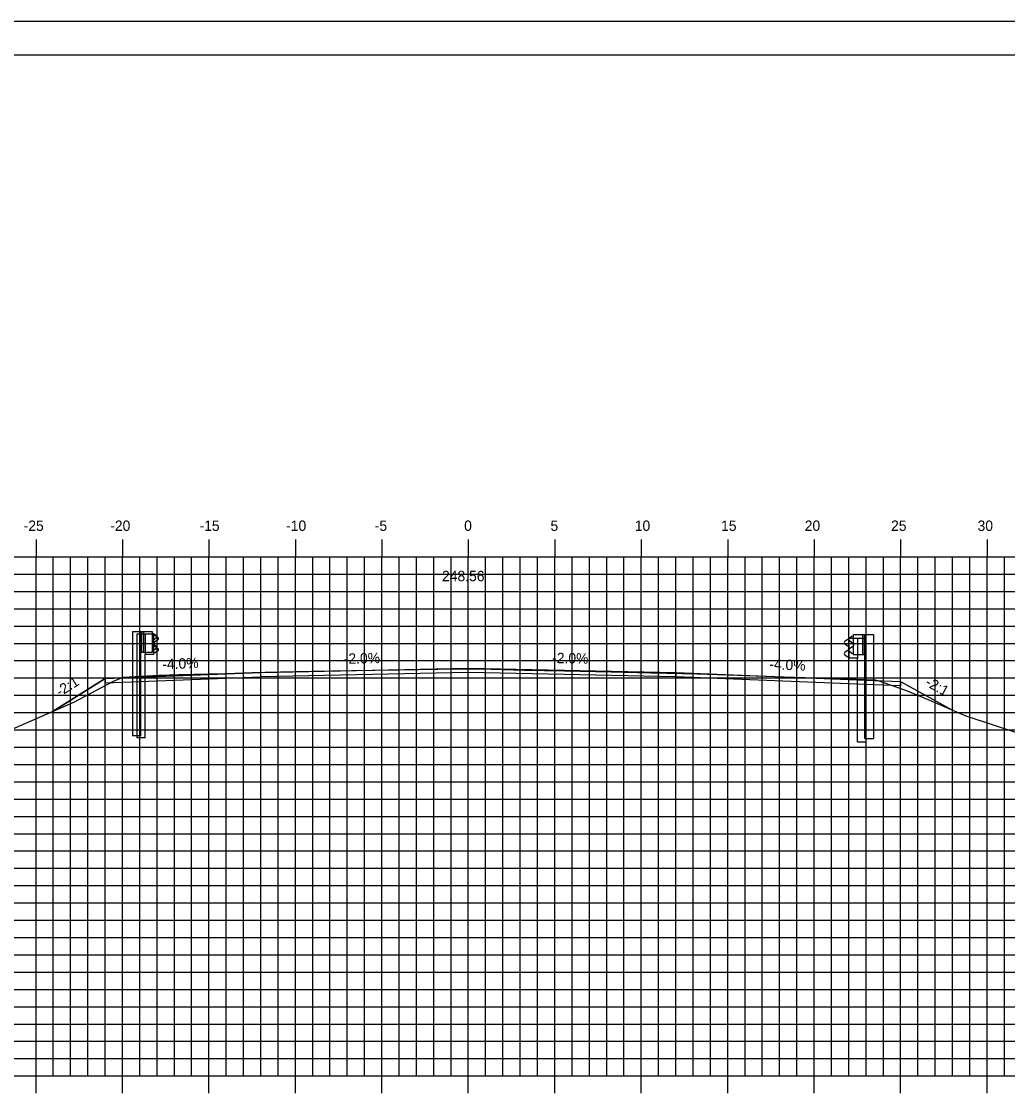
# Model space of a CAD drawing. Extents: x -22 to 1480, y -1511 to 8.
# Drawn here: x 162.3 to 219.3, y -1463.6 to -1401.4 of the extents above; entities that cross this region are included whole.
import ezdxf

# ---------------------------------------------------------------- set-up
doc = ezdxf.new("R2010")
doc.units = 0
for name, color, linetype in [('ANNOTATION', 7, 'Continuous'), ('BORDER', 7, 'Continuous'), ('D_Guardrail_Beam_Lt', 7, 'Continuous'), ('D_Guardrail_Beam_Rt', 7, 'Continuous'), ('D_Roadway_Centerline', 7, 'Continuous'), ('D_Roadway_Centerline_Text', 7, 'Continuous'), ('D_Roadway_Edge_Shoulder', 7, 'Continuous'), ('D_Roadway_Edge_TW', 7, 'Continuous'), ('D_Roadway_SlopeLines', 7, 'Continuous'), ('H_V ANNOTATION', 7, 'Continuous'), ('MAJOR', 7, 'Continuous'), ('MINOR', 7, 'Continuous'), ('PLOT BOUNDARY', 7, 'Continuous'), ('S_Guardrail_Beam', 7, 'Continuous'), ('S_Roadway_Centerline', 7, 'Continuous')]:
    doc.layers.add(name, color=color, linetype=linetype)

msp = doc.modelspace()

# ---------------------------------------------------------------- linework, layer by layer
at = {"layer": 'BORDER'}
msp.add_line((273.157, -1403.331), (113.157, -1403.331), dxfattribs=at)
at = {"layer": 'D_Guardrail_Beam_Lt'}
for p, q in [((168.727, -1436.668), (168.727, -1442.668)), ((169.198, -1436.668), (168.727, -1436.668)), ((169.886, -1436.668), (169.198, -1436.668)), ((169.198, -1436.668), (169.198, -1437.834)), ((169.261, -1436.668), (169.261, -1437.834)), ((169.365, -1436.668), (169.365, -1437.834)), ((169.886, -1437.834), (169.886, -1436.668)), ((169.886, -1436.751), (169.96, -1436.766)), ((170.119, -1437.015), (169.924, -1437.152)), ((169.976, -1436.772), (170.119, -1436.872)), ((169.96, -1437.737), (169.886, -1437.751)), ((169.89, -1437.216), (169.89, -1437.286)), ((169.924, -1437.351), (170.119, -1437.487)), ((170.119, -1437.63), (169.976, -1437.73)), ((169.198, -1437.834), (169.886, -1437.834)), ((169.219, -1442.668), (169.219, -1437.834)), ((169.219, -1442.668), (168.727, -1442.668))]:
    msp.add_line(p, q, dxfattribs=at)
for centre, major_axis, start_param, end_param in [((169.952, -1436.806), (0.0417, 0), 0.959931, 1.376053), ((170.069, -1436.944), (0.0877, 0), 5.323254, 7.243116), ((169.969, -1437.216), (-0.0789, 0), 5.323254, 6.283185), ((169.969, -1437.286), (-0.0789, 0), 6.283185, 7.243116), ((169.952, -1437.696), (0.0417, 0), 4.907132, 5.323254), ((170.069, -1437.558), (0.0877, 0), 5.323254, 7.243116)]:
    msp.add_ellipse(centre, major_axis=major_axis, ratio=0.995501, start_param=start_param, end_param=end_param, dxfattribs=at)
at = {"layer": 'D_Guardrail_Beam_Rt'}
for p, q in [((210.337, -1436.932), (210.194, -1437.032)), ((210.427, -1436.911), (210.353, -1436.926)), ((210.427, -1436.828), (211.115, -1436.828)), ((210.427, -1437.994), (210.427, -1436.828)), ((210.948, -1436.828), (210.948, -1437.994)), ((211.052, -1436.828), (211.052, -1437.994)), ((211.115, -1436.828), (211.586, -1436.828)), ((211.115, -1436.828), (211.115, -1437.994)), ((211.586, -1436.828), (211.586, -1442.828)), ((210.194, -1437.175), (210.389, -1437.312)), ((210.389, -1437.511), (210.194, -1437.647)), ((210.423, -1437.376), (210.423, -1437.446)), ((210.194, -1437.79), (210.337, -1437.89)), ((210.353, -1437.897), (210.427, -1437.911)), ((211.115, -1437.994), (210.427, -1437.994)), ((211.094, -1442.828), (211.094, -1437.994)), ((211.094, -1442.828), (211.586, -1442.828))]:
    msp.add_line(p, q, dxfattribs=at)
for centre, major_axis, start_param, end_param in [((210.244, -1437.104), (-0.0877, 0), 5.323254, 7.243116), ((210.361, -1436.966), (-0.0417, 0), 4.907132, 5.323254), ((210.244, -1437.718), (-0.0877, 0), 5.323254, 7.243116), ((210.344, -1437.376), (0.0789, 0), 0, 0.959931), ((210.344, -1437.446), (0.0789, 0), 5.323254, 6.283185), ((210.361, -1437.856), (-0.0417, 0), 0.959931, 1.376053)]:
    msp.add_ellipse(centre, major_axis=major_axis, ratio=0.995501, start_param=start_param, end_param=end_param, dxfattribs=at)
at = {"layer": 'D_Roadway_Centerline'}
msp.add_lwpolyline([(164.156, -1441.249), (167.156, -1439.371), (170.156, -1439.251), (176.156, -1439.011), (188.156, -1438.771), (200.156, -1439.011), (210.156, -1439.411), (213.156, -1439.531), (216.156, -1441.183)], dxfattribs=at)
at = {"layer": 'D_Roadway_Edge_Shoulder'}
for points in [[(176.156, -1439.011), (170.156, -1439.251), (170.156, -1439.251), (167.156, -1439.371), (167.156, -1439.621), (170.156, -1439.501), (170.156, -1439.501), (176.156, -1439.261)], [(200.156, -1439.011), (210.156, -1439.411), (210.156, -1439.411), (213.156, -1439.531), (213.156, -1439.781), (210.156, -1439.661), (210.156, -1439.661), (200.156, -1439.261)]]:
    msp.add_lwpolyline(points, close=True, dxfattribs=at)
at = {"layer": 'D_Roadway_Edge_TW'}
msp.add_lwpolyline([(176.156, -1439.261), (176.156, -1439.011), (188.156, -1438.771), (200.156, -1439.011), (200.156, -1439.261), (188.156, -1439.021)], close=True, dxfattribs=at)
at = {"layer": 'D_Roadway_SlopeLines'}
for points in [[(167.156, -1439.371), (164.156, -1441.249)], [(213.156, -1439.531), (216.156, -1441.183)]]:
    msp.add_lwpolyline(points, dxfattribs=at)
at = {"layer": 'MAJOR'}
for p, q in [((163.156, -1431.329), (163.156, -1432.331)), ((168.156, -1431.329), (168.156, -1432.331)), ((173.156, -1431.329), (173.156, -1432.331)), ((178.156, -1431.329), (178.156, -1432.331)), ((183.156, -1431.329), (183.156, -1432.331)), ((188.156, -1431.329), (188.156, -1432.331)), ((193.156, -1431.329), (193.156, -1432.331)), ((198.156, -1431.329), (198.156, -1432.331)), ((203.156, -1431.329), (203.156, -1432.331)), ((208.156, -1431.329), (208.156, -1432.331)), ((213.156, -1431.329), (213.156, -1432.331)), ((218.156, -1431.329), (218.156, -1432.331)), ((118.156, -1432.331), (258.156, -1432.331)), ((118.156, -1432.331), (258.156, -1432.331)), ((163.156, -1462.331), (163.156, -1432.331)), ((168.156, -1462.331), (168.156, -1432.331)), ((173.156, -1462.331), (173.156, -1432.331)), ((178.156, -1462.331), (178.156, -1432.331)), ((183.156, -1462.331), (183.156, -1432.331)), ((188.156, -1462.331), (188.156, -1432.331)), ((193.156, -1462.331), (193.156, -1432.331)), ((198.156, -1462.331), (198.156, -1432.331)), ((203.156, -1462.331), (203.156, -1432.331)), ((208.156, -1462.331), (208.156, -1432.331)), ((213.156, -1462.331), (213.156, -1432.331)), ((218.156, -1462.331), (218.156, -1432.331)), ((118.156, -1437.331), (258.156, -1437.331)), ((118.156, -1442.331), (258.156, -1442.331)), ((118.156, -1447.331), (258.156, -1447.331)), ((118.156, -1452.331), (258.156, -1452.331)), ((118.156, -1457.331), (258.156, -1457.331)), ((118.156, -1462.331), (258.156, -1462.331)), ((118.156, -1462.331), (258.156, -1462.331)), ((163.156, -1463.333), (163.156, -1462.331)), ((168.156, -1463.333), (168.156, -1462.331)), ((173.156, -1463.333), (173.156, -1462.331)), ((178.156, -1463.333), (178.156, -1462.331)), ((183.156, -1463.333), (183.156, -1462.331)), ((188.156, -1463.333), (188.156, -1462.331)), ((193.156, -1463.333), (193.156, -1462.331)), ((198.156, -1463.333), (198.156, -1462.331)), ((203.156, -1463.333), (203.156, -1462.331)), ((208.156, -1463.333), (208.156, -1462.331)), ((213.156, -1463.333), (213.156, -1462.331)), ((218.156, -1463.333), (218.156, -1462.331))]:
    msp.add_line(p, q, dxfattribs=at)
at = {"layer": 'MINOR'}
for p, q in [((164.156, -1462.331), (164.156, -1432.331)), ((165.156, -1462.331), (165.156, -1432.331)), ((166.156, -1462.331), (166.156, -1432.331)), ((167.156, -1462.331), (167.156, -1432.331)), ((169.156, -1462.331), (169.156, -1432.331)), ((170.156, -1462.331), (170.156, -1432.331)), ((171.156, -1462.331), (171.156, -1432.331)), ((172.156, -1462.331), (172.156, -1432.331)), ((174.156, -1462.331), (174.156, -1432.331)), ((175.156, -1462.331), (175.156, -1432.331)), ((176.156, -1462.331), (176.156, -1432.331)), ((177.156, -1462.331), (177.156, -1432.331)), ((179.156, -1462.331), (179.156, -1432.331)), ((180.156, -1462.331), (180.156, -1432.331)), ((181.156, -1462.331), (181.156, -1432.331)), ((182.156, -1462.331), (182.156, -1432.331)), ((184.156, -1462.331), (184.156, -1432.331)), ((185.156, -1462.331), (185.156, -1432.331)), ((186.156, -1462.331), (186.156, -1432.331)), ((187.156, -1462.331), (187.156, -1432.331)), ((189.156, -1462.331), (189.156, -1432.331)), ((190.156, -1462.331), (190.156, -1432.331)), ((191.156, -1462.331), (191.156, -1432.331)), ((192.156, -1462.331), (192.156, -1432.331)), ((194.156, -1462.331), (194.156, -1432.331)), ((195.156, -1462.331), (195.156, -1432.331)), ((196.156, -1462.331), (196.156, -1432.331)), ((197.156, -1462.331), (197.156, -1432.331)), ((199.156, -1462.331), (199.156, -1432.331)), ((200.156, -1462.331), (200.156, -1432.331)), ((201.156, -1462.331), (201.156, -1432.331)), ((202.156, -1462.331), (202.156, -1432.331)), ((204.156, -1462.331), (204.156, -1432.331)), ((205.156, -1462.331), (205.156, -1432.331)), ((206.156, -1462.331), (206.156, -1432.331)), ((207.156, -1462.331), (207.156, -1432.331)), ((209.156, -1462.331), (209.156, -1432.331)), ((210.156, -1462.331), (210.156, -1432.331)), ((211.156, -1462.331), (211.156, -1432.331)), ((212.156, -1462.331), (212.156, -1432.331)), ((214.156, -1462.331), (214.156, -1432.331)), ((215.156, -1462.331), (215.156, -1432.331)), ((216.156, -1462.331), (216.156, -1432.331)), ((217.156, -1462.331), (217.156, -1432.331)), ((219.156, -1462.331), (219.156, -1432.331)), ((118.156, -1433.331), (258.156, -1433.331)), ((118.156, -1434.331), (258.156, -1434.331)), ((118.156, -1435.331), (258.156, -1435.331)), ((118.156, -1436.331), (258.156, -1436.331)), ((118.156, -1438.331), (258.156, -1438.331)), ((118.156, -1439.331), (258.156, -1439.331)), ((118.156, -1440.331), (258.156, -1440.331)), ((118.156, -1441.331), (258.156, -1441.331)), ((118.156, -1443.331), (258.156, -1443.331)), ((118.156, -1444.331), (258.156, -1444.331)), ((118.156, -1445.331), (258.156, -1445.331)), ((118.156, -1446.331), (258.156, -1446.331)), ((118.156, -1448.331), (258.156, -1448.331)), ((118.156, -1449.331), (258.156, -1449.331)), ((118.156, -1450.331), (258.156, -1450.331)), ((118.156, -1451.331), (258.156, -1451.331)), ((118.156, -1453.331), (258.156, -1453.331)), ((118.156, -1454.331), (258.156, -1454.331)), ((118.156, -1455.331), (258.156, -1455.331)), ((118.156, -1456.331), (258.156, -1456.331)), ((118.156, -1458.331), (258.156, -1458.331)), ((118.156, -1459.331), (258.156, -1459.331)), ((118.156, -1460.331), (258.156, -1460.331)), ((118.156, -1461.331), (258.156, -1461.331))]:
    msp.add_line(p, q, dxfattribs=at)
at = {"layer": 'PLOT BOUNDARY'}
msp.add_lwpolyline([(105.063, -1511.39), (275.063, -1511.39), (275.063, -1401.39), (105.063, -1401.39)], close=True, dxfattribs=at)
at = {"layer": 'S_Guardrail_Beam'}
for p, q in [((168.985, -1436.79), (168.985, -1442.79)), ((169.477, -1436.79), (168.985, -1436.79)), ((169.967, -1436.79), (169.477, -1436.79)), ((169.477, -1436.79), (169.477, -1437.957)), ((169.967, -1437.957), (169.967, -1436.79)), ((169.967, -1436.863), (170.049, -1436.877)), ((170.209, -1437.127), (170.013, -1437.263)), ((170.065, -1436.884), (170.209, -1436.984)), ((210.071, -1437.119), (209.928, -1437.219)), ((210.17, -1437.098), (210.088, -1437.112)), ((210.17, -1437.025), (210.659, -1437.025)), ((210.17, -1438.191), (210.17, -1437.025)), ((210.659, -1437.025), (211.151, -1437.025)), ((210.659, -1437.025), (210.659, -1438.191)), ((211.151, -1437.025), (211.151, -1443.025)), ((169.98, -1437.328), (169.98, -1437.419)), ((170.013, -1437.483), (170.209, -1437.619)), ((170.209, -1437.762), (170.065, -1437.862)), ((209.928, -1437.362), (210.123, -1437.498)), ((210.123, -1437.718), (209.928, -1437.854)), ((210.157, -1437.563), (210.157, -1437.654)), ((169.477, -1442.79), (169.477, -1437.957)), ((169.477, -1437.957), (169.967, -1437.957)), ((170.049, -1437.869), (169.967, -1437.884)), ((209.928, -1437.997), (210.071, -1438.097)), ((210.088, -1438.104), (210.17, -1438.119)), ((210.659, -1438.191), (210.17, -1438.191)), ((210.659, -1443.025), (210.659, -1438.191)), ((169.477, -1442.79), (168.985, -1442.79)), ((210.659, -1443.025), (211.151, -1443.025))]:
    msp.add_line(p, q, dxfattribs=at)
for centre, major_axis, start_param, end_param in [((170.041, -1436.918), (0.0417, 0), 0.959931, 1.396263), ((170.158, -1437.056), (0.0877, 0), 5.323254, 7.243116), ((210.095, -1437.153), (-0.0417, 0), 4.886922, 5.323254), ((170.059, -1437.328), (-0.0789, 0), 5.323254, 6.283185), ((170.059, -1437.419), (-0.0789, 0), 6.283185, 7.243116), ((170.158, -1437.691), (0.0877, 0), 5.323254, 7.243116), ((209.978, -1437.29), (-0.0877, 0), 5.323254, 7.243116), ((210.078, -1437.563), (0.0789, 0), 0, 0.959931), ((210.078, -1437.654), (0.0789, 0), 5.323254, 6.283185), ((170.041, -1437.828), (0.0417, 0), 4.886922, 5.323254), ((209.978, -1437.926), (-0.0877, 0), 5.323254, 7.243116), ((210.095, -1438.063), (-0.0417, 0), 0.959931, 1.396263)]:
    msp.add_ellipse(centre, major_axis=major_axis, ratio=0.995501, start_param=start_param, end_param=end_param, dxfattribs=at)
at = {"layer": 'S_Roadway_Centerline'}
msp.add_lwpolyline([(142.335, -1450.792), (165.337, -1440.733), (167.638, -1439.523), (168.205, -1439.282), (170.283, -1439.177), (171.411, -1439.127), (174.084, -1439.064), (176.411, -1439.004), (179.089, -1438.946), (181.411, -1438.894), (184.094, -1438.854), (186.411, -1438.813), (187.038, -1438.805), (187.792, -1438.795), (189.478, -1438.831), (191.411, -1438.871), (193.72, -1438.921), (196.411, -1438.978), (198.717, -1439.03), (201.411, -1439.086), (203.713, -1439.17), (206.411, -1439.268), (209.445, -1439.364), (211.68, -1439.435), (211.828, -1439.483), (213.444, -1440.041), (214.413, -1440.436), (216.927, -1441.514), (220.143, -1442.576)], dxfattribs=at)
msp.add_lwpolyline([(142.335, -1450.792), (165.337, -1440.733), (167.638, -1439.523), (168.205, -1439.282), (170.283, -1439.177), (171.411, -1439.127), (174.084, -1439.064), (176.411, -1439.004), (179.089, -1438.946), (181.411, -1438.894), (184.094, -1438.854), (186.411, -1438.813), (187.038, -1438.805), (187.792, -1438.795), (189.478, -1438.831), (191.411, -1438.871), (193.72, -1438.921), (196.411, -1438.978), (198.717, -1439.03), (201.411, -1439.086), (203.713, -1439.17), (206.411, -1439.268), (209.445, -1439.364), (211.68, -1439.435), (211.828, -1439.483), (213.444, -1440.041), (214.413, -1440.436), (216.927, -1441.514), (220.143, -1442.576)], dxfattribs=at)

# ---------------------------------------------------------------- texts
at = {"layer": 'ANNOTATION'}
for s, rotation, p in [('-4.0%', 2.29061, (170.472, -1438.838)), ('-2.0%', 1.14576, (180.959, -1438.515)), ('-2.0%', 358.85424, (192.999, -1438.468)), ('-4.0%', 357.70939, (205.552, -1438.826)), ('-2:1', 32.04702, (164.535, -1440.433)), ('-2:1', 331.15743, (214.528, -1439.745))]:
    msp.add_text(s, height=0.6, rotation=rotation, dxfattribs=at).set_placement(p)
at = {"layer": 'D_Roadway_Centerline'}
for s, p in [('C', (188.151, -1438.771)), ('L', (188.156, -1438.778))]:
    msp.add_text(s, height=0.0146, dxfattribs=at).set_placement(p)
at = {"layer": 'D_Roadway_Centerline_Text'}
msp.add_text('248.56', height=0.6, dxfattribs=at).set_placement((186.637, -1433.739))
at = {"layer": 'H_V ANNOTATION'}
for s, p in [('-25', (162.442, -1430.831)), ('-20', (167.45, -1430.831)), ('-15', (172.613, -1430.831)), ('-10', (177.621, -1430.831)), ('-5', (182.747, -1430.831)), ('0', (187.915, -1430.831)), ('5', (192.907, -1430.831)), ('10', (197.782, -1430.831)), ('15', (202.774, -1430.831)), ('20', (207.61, -1430.831)), ('25', (212.602, -1430.831)), ('30', (217.605, -1430.831))]:
    msp.add_text(s, height=0.6, dxfattribs=at).set_placement(p)

doc.saveas('drawing.dxf')
